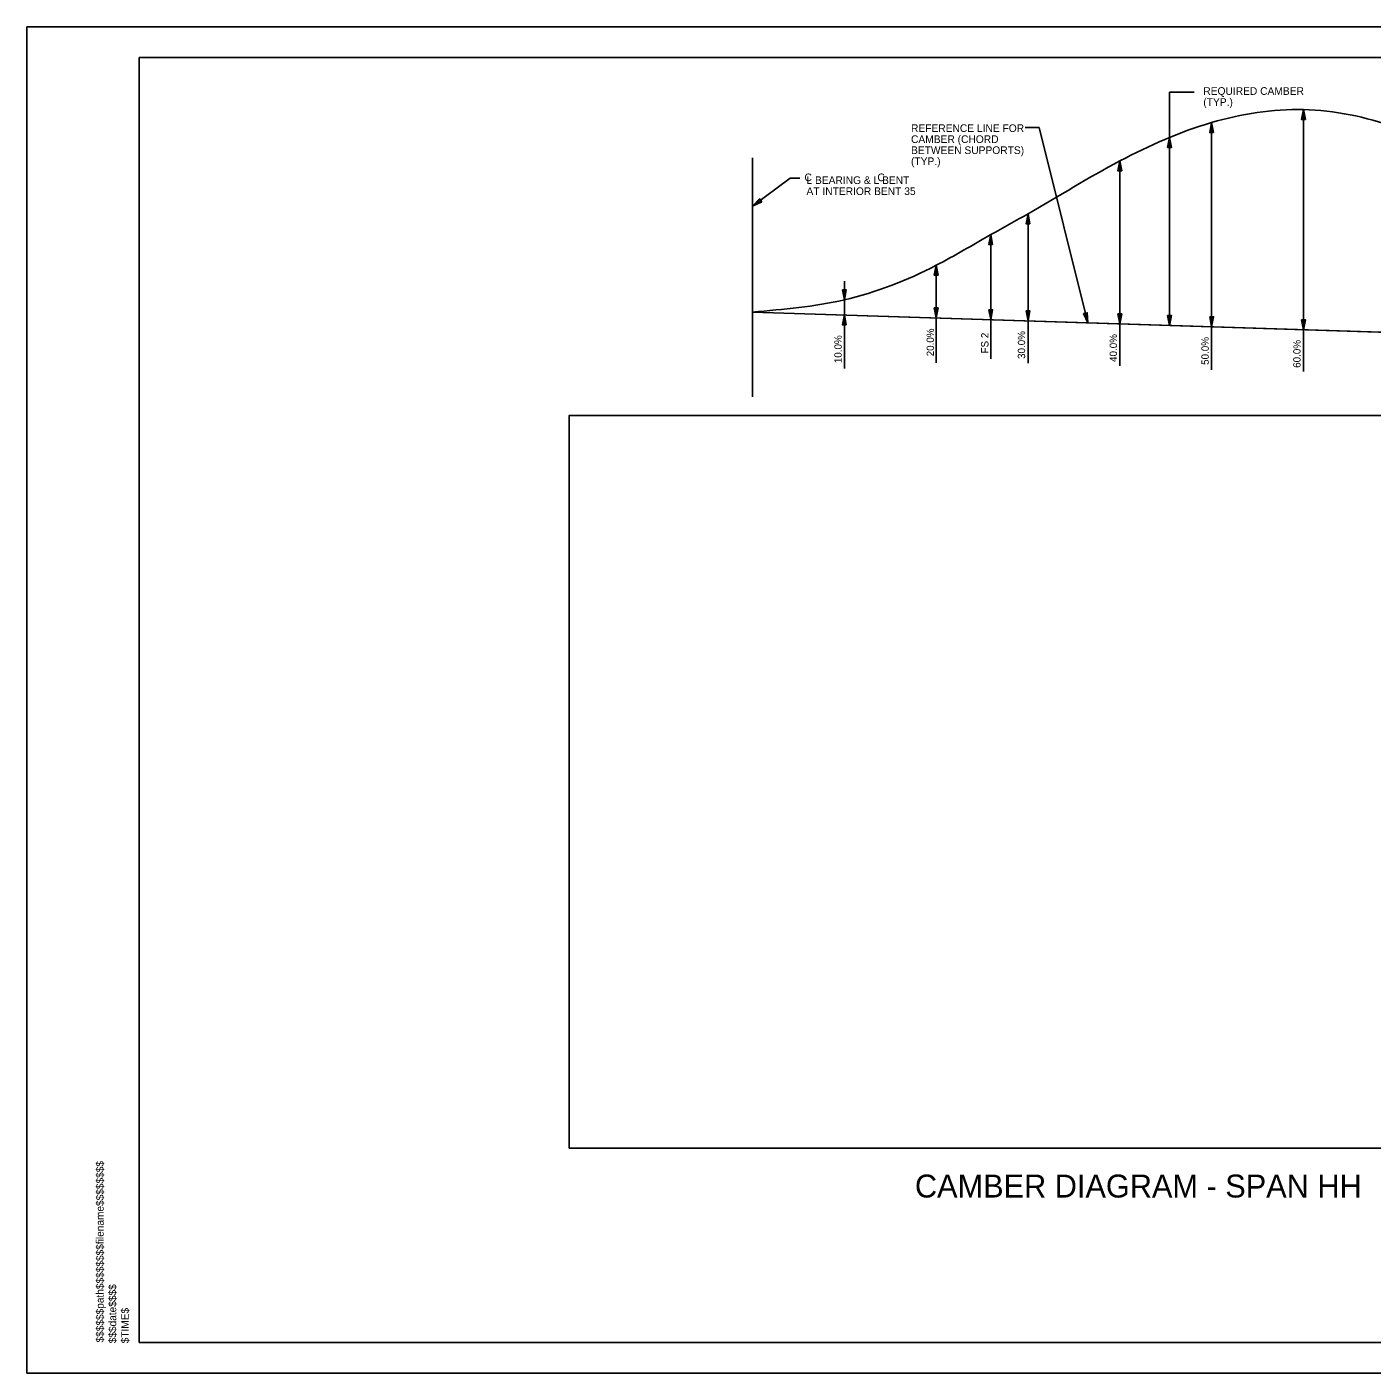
# Model space of a CAD drawing. Extents: x -133.1 to -97, y -1.7 to 20.3.
# Drawn here: x -133.14 to -111.16, y -1.69 to 20.31 of the extents above; entities that cross this region are included whole.
import ezdxf

# ---------------------------------------------------------------- set-up
doc = ezdxf.new("R2010")
doc.units = 0
for name, color, linetype in [('BR_AUTO DIMENSION', 7, 'Continuous'), ('BR_BORDER LINES', 7, 'Continuous'), ('BR_CENTER LINES', 7, 'Continuous'), ('BR_TABLE LINES', 7, 'Continuous'), ('BR_TEXT', 7, 'Continuous'), ('Default', 7, 'Continuous'), ('Level 31', 7, 'Continuous'), ('RD_SHT_ID', 7, 'Continuous')]:
    doc.layers.add(name, color=color, linetype=linetype)

msp = doc.modelspace()

# ---------------------------------------------------------------- linework, layer by layer
at = {"layer": 'BR_AUTO DIMENSION'}
for p, q in [((-114.473, 15.431), (-114.473, 19.243)), ((-114.473, 19.243), (-114.071, 19.243)), ((-116.829, 18.666), (-116.6, 18.666)), ((-116.6, 18.666), (-115.807, 15.474)), ((-120.672, 17.836), (-121.284, 17.377)), ((-120.511, 17.836), (-120.672, 17.836))]:
    msp.add_line(p, q, dxfattribs=at)
for points in [[(-112.253, 18.796), (-112.284, 18.958), (-112.315, 18.796)], [(-113.753, 18.583), (-113.784, 18.746), (-113.815, 18.583)], [(-114.504, 18.338), (-114.473, 18.5), (-114.441, 18.338)], [(-115.253, 17.956), (-115.284, 18.119), (-115.315, 17.956)], [(-121.136, 17.451), (-121.284, 17.377), (-121.174, 17.501)], [(-116.753, 17.093), (-116.784, 17.256), (-116.815, 17.093)], [(-117.362, 16.751), (-117.393, 16.914), (-117.424, 16.751)], [(-118.253, 16.251), (-118.284, 16.413), (-118.315, 16.251)], [(-119.815, 16.011), (-119.784, 15.849), (-119.753, 16.011)], [(-118.315, 15.716), (-118.284, 15.554), (-118.253, 15.716)], [(-117.424, 15.687), (-117.393, 15.525), (-117.362, 15.687)], [(-116.815, 15.668), (-116.784, 15.505), (-116.753, 15.668)], [(-115.876, 15.624), (-115.807, 15.474), (-115.816, 15.639)], [(-119.753, 15.439), (-119.784, 15.602), (-119.815, 15.439)], [(-115.315, 15.62), (-115.284, 15.457), (-115.253, 15.62)], [(-114.504, 15.594), (-114.473, 15.431), (-114.441, 15.594)], [(-113.815, 15.572), (-113.784, 15.409), (-113.753, 15.572)], [(-112.315, 15.523), (-112.284, 15.361), (-112.253, 15.523)], [(-124.284, 1.983), (-106.284, 1.983), (-106.284, 13.956), (-124.284, 13.956)]]:
    msp.add_lwpolyline(points, close=True, dxfattribs=at)
at = {"layer": 'BR_BORDER LINES'}
for p, q in [((-97.642, 19.809), (-131.308, 19.809)), ((-131.308, -1.191), (-131.308, 19.809)), ((-131.308, -1.191), (-97.642, -1.191))]:
    msp.add_line(p, q, dxfattribs=at)
at = {"layer": 'BR_CENTER LINES'}
msp.add_line((-121.284, 14.261), (-121.284, 18.168), dxfattribs=at)
at = {"layer": 'BR_TABLE LINES'}
for p, q in [((-112.284, 14.679), (-112.284, 18.958)), ((-113.784, 14.706), (-113.784, 18.746)), ((-115.284, 14.771), (-115.284, 18.119)), ((-116.784, 14.816), (-116.784, 17.256)), ((-117.393, 14.882), (-117.393, 16.914)), ((-118.284, 14.821), (-118.284, 16.413)), ((-119.784, 14.728), (-119.784, 16.155)), ((-121.285, 15.65), (-106.284, 15.168))]:
    msp.add_line(p, q, dxfattribs=at)
msp.add_spline([(-121.285, 15.65), (-119.785, 15.849), (-118.285, 16.413), (-117.393, 16.914), (-116.784, 17.256), (-115.284, 18.119), (-113.784, 18.746), (-112.284, 18.958), (-110.784, 18.666), (-109.284, 17.866), (-107.784, 16.643), (-106.284, 15.168)], degree=3, dxfattribs=at)
at = {"layer": 'Default'}
msp.add_lwpolyline([(-121.285, 15.65), (-106.284, 15.168)], dxfattribs=at)
at = {"layer": 'Level 31'}
msp.add_lwpolyline([(-133.141, -1.691), (-97.141, -1.691), (-97.141, 20.309), (-133.141, 20.309)], close=True, dxfattribs=at)

# ---------------------------------------------------------------- texts
at = {"layer": 'BR_AUTO DIMENSION'}
for s, p in [('(TYP.)', (-113.92, 19.019)), ('REQUIRED CAMBER', (-113.92, 19.199)), ('REFERENCE LINE FOR', (-118.696, 18.592)), ('CAMBER (CHORD', (-118.696, 18.412)), ('BETWEEN SUPPORTS)', (-118.696, 18.232)), ('(TYP.)', (-118.696, 18.052)), ('C', (-120.436, 17.788)), ('L BEARING & L BENT', (-120.404, 17.742)), ('C', (-119.245, 17.788)), ('AT INTERIOR BENT 35', (-120.404, 17.562))]:
    msp.add_text(s, height=0.125, dxfattribs=at).set_placement(p)
at = {"layer": 'BR_TEXT'}
for s, p in [('10.0%', (-119.828, 14.814)), ('20.0%', (-118.321, 14.926)), ('FS 2', (-117.43, 14.973)), ('30.0%', (-116.831, 14.883)), ('40.0%', (-115.331, 14.834)), ('50.0%', (-113.831, 14.786)), ('60.0%', (-112.331, 14.738))]:
    msp.add_text(s, height=0.12, rotation=90, dxfattribs=at).set_placement(p)
msp.add_text('CAMBER DIAGRAM - SPAN HH', height=0.375, dxfattribs=at).set_placement((-118.632, 1.178))
at = {"layer": 'RD_SHT_ID'}
for s, height, p in [('$$$$$$path$$$$$$$$filename$$$$$$$$', 0.12347, (-131.887, -1.191)), ('$$$date$$$$', 0.12347, (-131.682, -1.204)), ('$TIME$', 0.1235, (-131.477, -1.204))]:
    msp.add_text(s, height=height, rotation=90, dxfattribs=at).set_placement(p)

doc.saveas('drawing.dxf')
